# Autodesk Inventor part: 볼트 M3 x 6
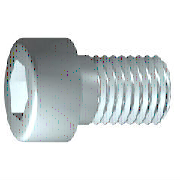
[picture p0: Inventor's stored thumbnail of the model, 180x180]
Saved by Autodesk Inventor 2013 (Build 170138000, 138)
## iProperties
IsCustomPart: 1
Created: 2012-02
Part Number: 볼트 M3 x 6
Material: 강철, 연강
Description: 원통형 머리 캡 나사
Document SubType Name: Modeling
Standard: JIS B 1176
Designer: mdu-01
Standards Organization: JIS
Language: ko-KR
Size Designation: M3 x 6
Categories: <MemberInstance><Categories><Category DisplayName="조임쇠" InternalName="e4da775c-781d-43d5-af7c-5136215cf5a6" Mnemonic="FSTN"><Category DisplayName="볼트" InternalN
Density: 1 g/cm^3
Author: mdu-01
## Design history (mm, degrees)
sketch "스케치1"
  geometry: L1 (-0.867, 0)-(6, 0); L2 (6, 0)-(6, 1.5); L3 (6, 1.5)-(1.25, 1.5); L4 (1.25, 1.5)-(0.943, 1.5); L5 (0.943, 1.5)-(0, 1.5); L6 (0, 1.5)-(0, 2.75); L7 (0, 2.75)-(-3, 2.75); L8 (-3, 2.75)-(-3, 1.443); L9 (-3, 1.443)-(-1.7, 1.443); L10 (-1.7, 1.443)-(-0.867, 0); L11 (-4.8, 0)-(7.8, 0) reference; L12 (0, -0.55)-(0, 3.3) reference; L13 (1.25, 1.5)-(0, 1.5)
  constraints: 22 end point, 6 parallel, 2 collinear, 2 perpendicular, 1 horizontal, 1 point on line
  dimensions: "d1" = 4.75 distance from line of L3.end L2 (= GEL); "d2" = 0.30683 distance of L4.end L3.end (computed from GAL); "d3" = 3 distance between parallel lines of L8 L6 (= KOH); "d4" = 1.3 distance of L8.end L9.end (= INTI); "d5" = 60 deg angle of L10 L1; "d6" = 3 diameter of L3 L1 (= GD); "d7" = 3 diameter of L5 L1 (= BDM); "d8" = 2.88675 diameter of L9 L1 (= 1.1547 x SW); "d9" = 5.5 diameter of L7 L1 (= KOD); "d26" = 6 distance between parallel lines of L12 L2 (= NLG)
revolve "본체" sketch "스케치1" stored, may be unused: angle "d10" = 90 deg
sketch "스케치2"
  geometry: L1 (0, -3.85)-(0, 3.85) reference; L2 (-3.85, 0)-(3.85, 0) reference; L3 (1.443, 0)-(0.722, -1.25); L4 (0.722, -1.25)-(-0.722, -1.25); L5 (-0.722, -1.25)-(-1.443, 0); L6 (-1.443, 0)-(-0.722, 1.25); L7 (-0.722, 1.25)-(0.722, 1.25); L8 (0.722, 1.25)-(1.443, 0); 2 further points
  constraints: 12 end point, 1 coincident, 1 horizontal alignment, 1 point on line, 12 other
extrude "슬롯" join sketch "스케치2" stored distance "d11" = 10; taper "d12" = 0 deg
workplane "Work Plane1"
fillet "Fillet2" dims "d30" = 0.1 (= R)
body "Solid1"
fillet "모깎기1" dims "d17" = 0.3 (= RR)
feature "스레드" dims "d13" = 4.75 (= GEL), "d14" = 0
chamfer "모따기1" distance "d15" = 0.30673 (= -0.5 x SPD + 0.5 x GD); stored, may be unused: second distance "d16" = 0.30673 (= GUL), angle "d27" = 45 deg
other parameters: "GD" = 3 (= NND) [user parameter; used in 2 equation terms], "NLG" = 6 [user parameter; used in 1 equation term], "GEL" = 4.75 [user parameter; used in 2 equation terms], "KOD" = 5.5 [user parameter; used in 1 equation term], "KOH" = 3 [user parameter; used in 1 equation term], "INTI" = 1.3 [user parameter; used in 1 equation term], "GAL" = 0.30673 (= 0.61345 x PTC) [user parameter; used in 1 equation term], "GUL" = 0.30673 (= 0.61345 x PTC) [user parameter; used in 1 equation term], "BDM" = 3 (= NND) [user parameter; used in 1 equation term], "SW" = 2.5 [user parameter; used in 2 equation terms], "RR" = 0.3 [user parameter; used in 1 equation term], "SPD" = 2.38655 (= NND - 1.2269 x PTC) [user parameter; used in 1 equation term], "d19" = 0, "d28" = 0, "d29" = 0, "R" = 0.1 [user parameter; used in 1 equation term], "PHH" = 0.1 [user parameter], "GD1" = 2.38655 (= THREADDIA - 1.2269 x PTC) [user parameter], "THREADDIA" = 3 [user parameter; used in 1 equation term], "FAWI" = 45 deg [user parameter], "PTC" = 0.5 [user parameter; used in 5 equation terms], "NND" = 3 [user parameter; used in 3 equation terms], "TOA" = 30 deg [user parameter], "E0" = 2.8875 (= 1.155 x SW) [user parameter]
